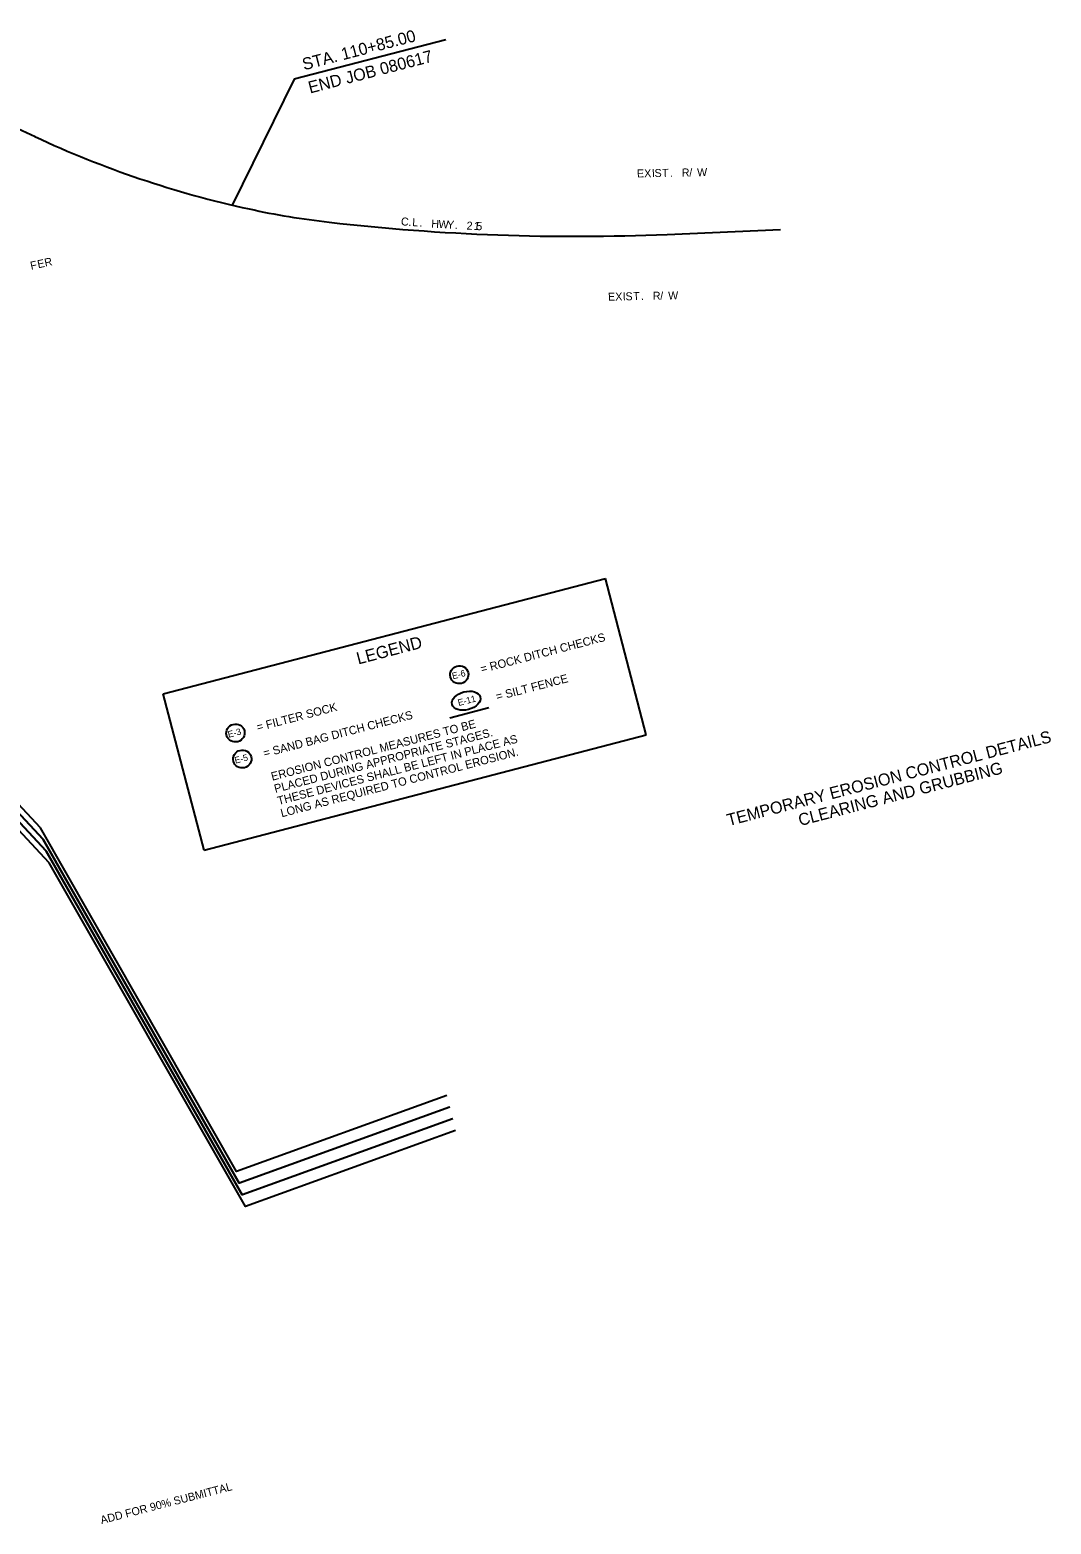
# Model space of a CAD drawing. Extents: x 833706 to 836451, y 495860 to 497794.
# Drawn here: x 835686 to 836451, y 495860 to 496980 of the extents above; entities that cross this region are included whole.
import ezdxf

# ---------------------------------------------------------------- set-up
doc = ezdxf.new("R2010")
doc.units = 0
for name, color, linetype in [('1', 7, 'Continuous'), ('44', 7, 'Continuous'), ('60', 7, 'Continuous'), ('8', 7, 'Continuous'), ('Level 1', 7, 'Continuous'), ('Level 44', 7, 'Continuous'), ('R_Draft', 7, 'Continuous'), ('R_Horz Alg', 7, 'Continuous')]:
    doc.layers.add(name, color=color, linetype=linetype)

msp = doc.modelspace()

# ---------------------------------------------------------------- linework, layer by layer
at = {"layer": '1'}
for p, q in [((835785.5, 496482.5), (836117.1, 496569)), ((836147.6, 496451.9), (836117.1, 496569)), ((835816.1, 496365.4), (835785.5, 496482.5)), ((835816.1, 496365.4), (836147.6, 496451.9))]:
    msp.add_line(p, q, dxfattribs=at)
at = {"layer": '8'}
for p, q in [((835997.4, 496972.9), (835883.8, 496943.4)), ((835883.8, 496943.4), (835837.1, 496848.9))]:
    msp.add_line(p, q, dxfattribs=at)
at = {"layer": 'Level 1'}
for centre, major_axis, ratio in [((836007.5, 496496.9), (-6.66, -1.74), 0.97521), ((836012.7, 496477.4), (10.6, 2.8), 0.622952), ((835839.7, 496453.2), (-6.66, -1.74), 0.97521), ((835844.8, 496433.7), (-6.66, -1.74), 0.97521)]:
    msp.add_ellipse(centre, major_axis=major_axis, ratio=ratio, dxfattribs=at)
at = {"layer": 'Level 44'}
msp.add_lwpolyline([(836000.5, 496464.5), (836029.6, 496472.2)], dxfattribs=at)
at = {"layer": 'R_Draft'}
for points in [[(835693.4, 496382.1), (835493.3, 496596.9), (835097.2, 496709.9)], [(835695.5, 496373.3), (835495.4, 496588.1), (835099.3, 496701.1)], [(835695.7, 496373.4), (835495.6, 496588.2), (835099.4, 496701.2)], [(835695.7, 496373.4), (835495.6, 496588.2), (835099.4, 496701.2)], [(835697.8, 496364.6), (835497.7, 496579.4), (835101.5, 496692.4)], [(835697.8, 496364.6), (835497.7, 496579.4), (835101.5, 496692.4)], [(835698, 496364.7), (835497.9, 496579.5), (835101.7, 496692.5)], [(835700.1, 496355.9), (835500, 496570.7), (835103.8, 496683.7)], [(835998.2, 496181.5), (835840.4, 496124.5), (835693.4, 496382.1)], [(836000.3, 496172.7), (835842.5, 496115.8), (835695.5, 496373.3)], [(836000.4, 496172.8), (835842.7, 496115.8), (835695.7, 496373.4)], [(836000.4, 496172.8), (835842.7, 496115.8), (835695.7, 496373.4)], [(836002.5, 496164), (835844.8, 496107.1), (835697.8, 496364.6)], [(836002.6, 496164), (835844.8, 496107.1), (835697.8, 496364.6)], [(836002.7, 496164.1), (835845, 496107.1), (835698, 496364.7)], [(836004.8, 496155.3), (835847.1, 496098.4), (835700.1, 496355.9)]]:
    msp.add_lwpolyline(points, dxfattribs=at)
at = {"layer": 'R_Horz Alg'}
for p, q in [((835657.7, 496915), (835689.4, 496900.2)), ((836163.3, 496826.9), (836248.3, 496830.5))]:
    msp.add_line(p, q, dxfattribs=at)
for centre, radius, start, end in [((836012.5, 497592.4), 763.9, 244.975, 257.7067), ((835978.3, 497435.3), 603.1, 257.7067, 263.4972), ((836095.4, 498462.5), 1637, 263.4972, 272.3792)]:
    msp.add_arc(centre, radius, start, end, dxfattribs=at)

# ---------------------------------------------------------------- texts
at = {"layer": '44'}
msp.add_text('ADD FOR 90% SUBMITTAL', height=6, rotation=14.5644, dxfattribs=at).set_placement((835739.3, 495860.2))
at = {"layer": '60'}
for s, p in [('TEMPORARY EROSION CONTROL DETAILS', (836209.5, 496383.4)), ('CLEARING AND GRUBBING', (836263.1, 496383.4))]:
    msp.add_text(s, height=9, rotation=14.5731, dxfattribs=at).set_placement(p)
at = {"layer": '8'}
for s, height, rotation, p in [('STA. 110+85.00', 9, 14.5557, (835891.1, 496949.9)), ('END JOB 080617', 9, 14.5557, (835895.6, 496932.5)), ('E', 6, 1.1141, (836140.8, 496869.6)), ('X', 6, 1.1141, (836146.2, 496869.7)), ('I', 6, 1.1141, (836152, 496869.9)), ('S', 6, 1.1141, (836154, 496869.9)), ('T', 6, 1.1141, (836159.6, 496870)), ('R', 6, 1.1141, (836174.4, 496870.3)), ('/', 6, 1.1141, (836180.1, 496870.4)), ('W', 6, 1.1141, (836185.9, 496870.5)), ('.', 6, 1.1141, (836165.5, 496870.1)), ('C', 6, 355.4729, (835963.6, 496833.8)), ('.', 6, 355.6717, (835969.2, 496833.4)), ('L', 6, 355.7744, (835972.1, 496833.2)), ('.', 6, 355.9633, (835977.5, 496832.8)), ('H', 6, 356.2763, (835986.4, 496832.1)), ('W', 6, 356.4652, (835991.8, 496831.8)), ('Y', 6, 356.6905, (835998.2, 496831.4)), ('.', 6, 356.8926, (836004, 496831.1)), ('2', 6, 357.2057, (836012.9, 496830.6)), ('1', 6, 357.3945, (836018.3, 496830.3)), ('5', 6, 357.4641, (836020.2, 496830.2)), ('E', 6, 12.1978, (835691.8, 496801.5)), ('R', 6, 12.1978, (835697.1, 496802.7)), ('F', 6, 12.1978, (835686.5, 496800.4)), ('E', 6, 1.1141, (836119.1, 496777.2)), ('X', 6, 1.1141, (836124.5, 496777.3)), ('I', 6, 1.1141, (836130.2, 496777.4)), ('S', 6, 1.1141, (836132.2, 496777.5)), ('T', 6, 1.1141, (836137.9, 496777.6)), ('.', 6, 1.1141, (836143.7, 496777.7)), ('R', 6, 1.1141, (836152.7, 496777.9)), ('/', 6, 1.1141, (836158.3, 496778)), ('W', 6, 1.1141, (836164.2, 496778.1))]:
    msp.add_text(s, height=height, rotation=rotation, dxfattribs=at).set_placement(p)
at = {"layer": 'Level 1'}
for s, height, p in [('= ROCK DITCH CHECKS', 6.25, (836024.3, 496498)), ('E-6 ', 4.88, (836002.8, 496493.4)), ('= SILT FENCE', 6.25, (836035.9, 496477.4)), ('= FILTER SOCK', 6.25, (835856.4, 496454.4)), ('E-11 ', 4.88, (836007.1, 496473.4)), ('= SAND BAG DITCH CHECKS', 6.25, (835861.5, 496434.9)), ('EROSION CONTROL MEASURES TO BE', 6.25, (835867.3, 496417.4)), ('E-3 ', 4.88, (835834.6, 496449.6)), ('PLACED DURING APPROPRIATE STAGES. ', 6.25, (835869.6, 496408.3)), ('THESE DEVICES SHALL BE LEFT IN PLACE AS ', 6.25, (835872, 496399.2)), ('LONG AS REQUIRED TO CONTROL EROSION.', 6.25, (835874.4, 496390)), ('E-5 ', 4.88, (835839.7, 496430.2))]:
    msp.add_text(s, height=height, rotation=14.6224, dxfattribs=at).set_placement(p)
at = {"layer": 'Level 44'}
msp.add_text('LEGEND', height=9.14, rotation=14.6224, dxfattribs=at).set_placement((835931.8, 496504.5))

doc.saveas('drawing.dxf')
